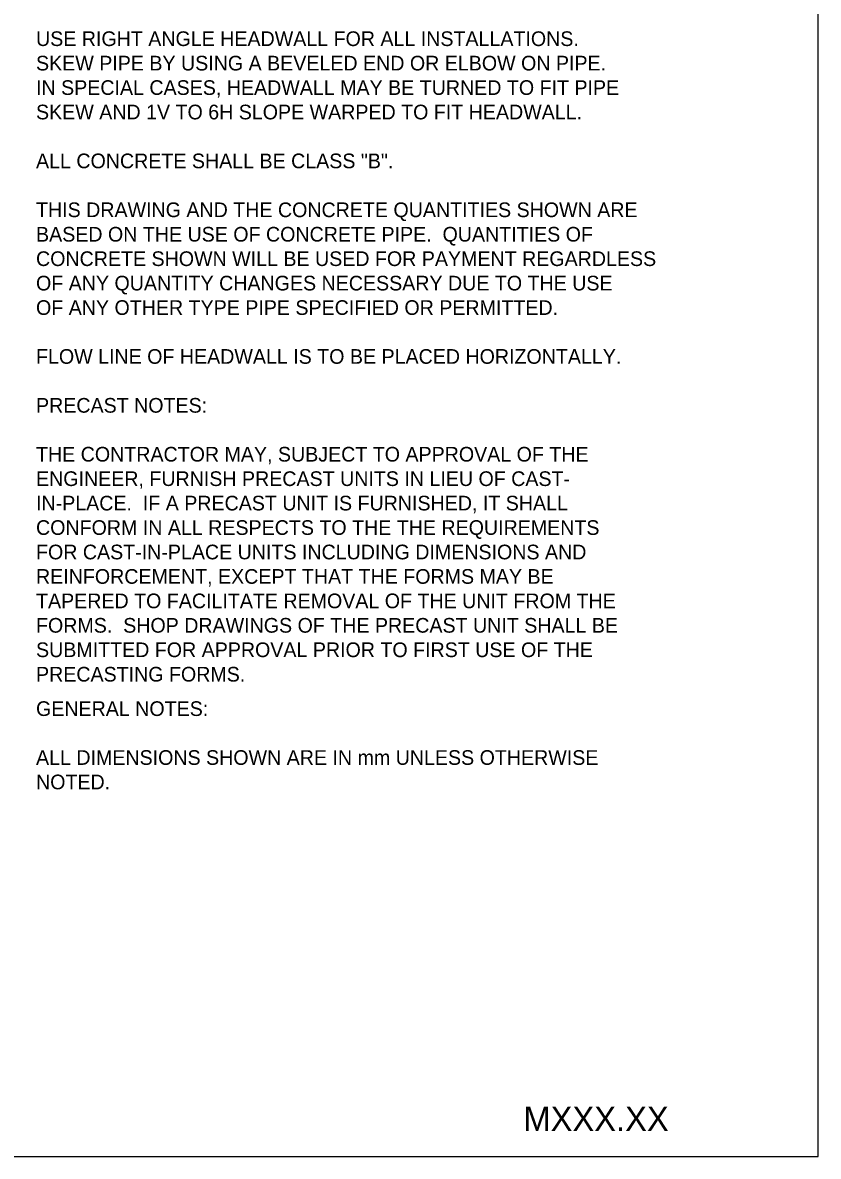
# Model space of a CAD drawing. Extents: x -439.1 to -407.9, y -458.1 to -436.2.
# Drawn here: x -416 to -407.86, y -458.05 to -446.46 of the extents above; entities that cross this region are included whole.
import ezdxf

# ---------------------------------------------------------------- set-up
doc = ezdxf.new("R2010")
doc.units = 0
for name, color, linetype in [('Bridge-Named Boundary', 7, 'Continuous'), ('Level 45', 7, 'Continuous'), ('Level 46', 7, 'Continuous')]:
    doc.layers.add(name, color=color, linetype=linetype)

msp = doc.modelspace()

# ---------------------------------------------------------------- linework, layer by layer
at = {"layer": 'Bridge-Named Boundary'}
msp.add_lwpolyline([(-439.109, -458.051), (-407.859, -458.051), (-407.859, -437.676), (-439.109, -437.676)], close=True, dxfattribs=at)

# ---------------------------------------------------------------- texts
at = {"layer": 'Level 45'}
for s, p in [('USE RIGHT ANGLE HEADWALL FOR ALL INSTALLATIONS.  ', (-415.859, -446.695)), ('SKEW PIPE BY USING A BEVELED END OR ELBOW ON PIPE.  ', (-415.859, -446.945)), ('IN SPECIAL CASES, HEADWALL MAY BE TURNED TO FIT PIPE ', (-415.859, -447.195)), ('SKEW AND 1V TO 6H SLOPE WARPED TO FIT HEADWALL.', (-415.859, -447.445)), ('ALL CONCRETE SHALL BE CLASS "B".', (-415.859, -447.945)), ('THIS DRAWING AND THE CONCRETE QUANTITIES SHOWN ARE ', (-415.859, -448.445)), ('BASED ON THE USE OF CONCRETE PIPE.  QUANTITIES OF ', (-415.859, -448.695)), ('CONCRETE SHOWN WILL BE USED FOR PAYMENT REGARDLESS ', (-415.859, -448.945)), ('OF ANY QUANTITY CHANGES NECESSARY DUE TO THE USE ', (-415.859, -449.195)), ('OF ANY OTHER TYPE PIPE SPECIFIED OR PERMITTED.', (-415.859, -449.445)), ('FLOW LINE OF HEADWALL IS TO BE PLACED HORIZONTALLY.', (-415.859, -449.945)), ('PRECAST NOTES:', (-415.859, -450.445)), ('THE CONTRACTOR MAY, SUBJECT TO APPROVAL OF THE ', (-415.859, -450.945)), ('ENGINEER, FURNISH PRECAST UNITS IN LIEU OF CAST-', (-415.859, -451.195)), ('IN-PLACE.  IF A PRECAST UNIT IS FURNISHED, IT SHALL ', (-415.859, -451.445)), ('CONFORM IN ALL RESPECTS TO THE THE REQUIREMENTS ', (-415.859, -451.695)), ('FOR CAST-IN-PLACE UNITS INCLUDING DIMENSIONS AND ', (-415.859, -451.945)), ('REINFORCEMENT, EXCEPT THAT THE FORMS MAY BE ', (-415.859, -452.195)), ('TAPERED TO FACILITATE REMOVAL OF THE UNIT FROM THE ', (-415.859, -452.445)), ('FORMS.  SHOP DRAWINGS OF THE PRECAST UNIT SHALL BE ', (-415.859, -452.695)), ('SUBMITTED FOR APPROVAL PRIOR TO FIRST USE OF THE ', (-415.859, -452.945)), ('PRECASTING FORMS.', (-415.859, -453.195))]:
    msp.add_text(s, height=0.15, dxfattribs=at).set_placement(p)
at = {"layer": 'Level 46'}
for s, height, p in [('GENERAL NOTES:', 0.15, (-415.859, -453.547)), ('ALL DIMENSIONS SHOWN ARE IN mm UNLESS OTHERWISE ', 0.15, (-415.859, -454.047)), ('NOTED.', 0.15, (-415.859, -454.297)), ('MXXX.XX', 0.25, (-410.875, -457.792))]:
    msp.add_text(s, height=height, dxfattribs=at).set_placement(p)

doc.saveas('drawing.dxf')
